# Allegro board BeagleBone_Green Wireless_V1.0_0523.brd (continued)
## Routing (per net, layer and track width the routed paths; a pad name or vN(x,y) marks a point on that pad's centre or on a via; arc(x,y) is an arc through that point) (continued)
BT_AUD_CLK: length 8
  TOP w0.121: U21.1 56.5,107.33 56.89,106.94 59.27,106.94 59.44,106.78 59.44,104.65 TP13.1 60.31,104.3 U18.60
BT_AUD_FSYNC: length 6.2
  TOP w0.121: U21.3 58.2,108.71 59.18,107.72 59.18,107.38 59.68,106.88 59.68,105.9 TP12.1 60.62,105.7 U18.58
BT_AUD_IN: length 5.1
  TOP w0.121: U18.56 60.89,107.1 60.74,107.25 60.49,107.25 60.1,107.65 TP10.1 59.69,108.17 59.69,108.3 58.64,109.35 58.39,109.35 58.04,109.71 U21.5
BT_AUD_OUT: length 5.5
  TOP w0.121: U18.57 TP11.1 59.97,106.8 59.97,106.94 59.44,107.48 59.44,108.18 58.51,109.11 58.29,109.11 58.19,109.21 U21.4
BT_EN: length 11.9
  TOP w0.121: v1(68.17,111.25) 67.86,111.56 67.86,111.58 67.63,111.82 67.56,111.82 67.44,111.94 U18.41
  BOTTOM w0.121: Q3.1 62.98,107.53 64.46,106.05 65.5,106.05 66.73,107.28 66.73,108.23 67.02,108.51 67.02,109.25 67.46,109.69 R188.1 67.46,109.78 67.78,110.1 67.79,110.1 68.17,110.48 v1(68.17,111.25)
BT_HCI_CTS: length 1.3
  TOP w0.121: R184.1 58.65,111.21 U21.8
BT_HCI_RTS: length 1.5
  TOP w0.121: U21.9 58.27,111.71 R183.1
BT_HCI_RX: length 1.4
  TOP w0.121: U21.6 58.04,110.21 58.42,109.83 R186.1
BT_HCI_TX: length 1.3
  TOP w0.121: R185.1 58.69,110.71 U21.7
CAP_VBB_MPU: length 4.2
  TOP w0.121: v1(46.32,88.73) 46.33,88.75 U5.C10
  BOTTOM w0.121: C91.1 46.8,87.54 46.32,88.02 v1(46.32,88.73)
CAP_VDD_SRAM_CORE: length 5.2
  TOP w0.121: U5.D9 v1(47.92,89.54)
  BOTTOM w0.121: C89.1 47.75,87.6 48.32,88.17 48.32,89.13 v1(47.92,89.54)
CAP_VDD_SRAM_MPU: length 5
  TOP w0.121: v1(45.52,89.54) U5.D11
  BOTTOM w0.121: v1(45.52,89.54) 45.92,89.13 45.92,85.39 C90.1
CLKOUT2: length 112.1
  TOP w0.121: v1(49.58,78.31) 49.02,77.75 49.02,75.54 49.03,75.53 49.03,75.44 49.83,74.64 56.78,74.64 59.16,72.26 61.12,72.26 61.77,71.6 66.68,71.6 67.61,70.66 69.88,70.66 70.56,69.98 70.56,68.2 71.73,67.03 P9.41
  LYR4 w0.127: v1(50.14,107.82) 49.76,107.82 49.58,107.65 42.98,107.65 38.35,103.02 38.35,103.02
  LYR4 w0.133: v1(35.56,83.18) 35.61,83.23 35.61,83.37 35.55,83.44 35.55,86.65 34.99,87.2 34.99,88.28 35.75,89.04 35.75,93.48 37.2,94.93 37.2,99.61 36.83,99.98 36.83,101.73 36.65,101.9 36.65,102.48 37.19,103.02 38.35,103.02
  BOTTOM w0.121: v1(49.58,78.31) 49.45,78.44 49.3,78.44 48.97,78.77 43.94,78.77 42.99,79.72 42.99,82.72 43.94,83.67 R20.1 R19.2 42.48,84.81 42.48,85.76 42.29,85.95 41.53,85.95 41.29,85.72 37.68,85.72 37.07,85.1 37.07,84.56 37.48,84.14 37.48,83.45 37.07,83.03 37.07,82.84 37.06,82.83 ; 37.06,82.83 35.91,82.83 v1(35.56,83.18) ; 37.06,82.83 37.31,82.59 P2.18 ; U22.20 65.67,105.35 65.46,105.56 63.5,105.56 63,106.06 61.49,106.06 61.32,106.24 58.63,106.24 56.82,108.05 56.41,108.05 56.4,108.04 55.03,108.04 54.17,107.17
  BOTTOM w0.127: v1(50.14,107.82) 50.14,107.61 50.86,106.9 52.17,106.9 52.44,107.17 54.17,107.17
CLKOUT_SRC: length 5.1
  TOP w0.121: U5.D14 v1(43.12,89.54)
  BOTTOM w0.121: R19.1 42.99,88.11 42.72,88.39 42.72,89.13 v1(43.12,89.54)
DDR_A0: length 23.9
  TOP w0.121: U5.F3 v1(52.72,91.14) ; v1(62.9,85.89) U12.N3
  LYR3 w0.133: v1(55.24,88.24) 54.74,88.24 54.61,88.11 54.61,86.33 56.26,84.68 56.26,84.43 58.42,82.27 62.99,82.27 63.75,83.03 63.75,85.83 63.37,86.21 63.21,86.21 v1(62.9,85.89)
  BOTTOM w0.121: v1(52.72,91.14) 53.12,91.54 53.72,91.54 53.98,91.29 53.98,89.51 v1(55.24,88.24)
DDR_A1: length 24.1
  TOP w0.121: U5.H1 55.94,93.14 57.98,91.1 59.12,91.1 60.32,89.89 v1(60.32,89) ; v1(66.9,85.09) U12.P7
  LYR3 w0.121: 61.59,89 61.9,88.69 63.07,88.69
  LYR3 w0.133: v1(66.9,85.09) 66.54,85.45 66.29,85.45 66.17,85.32 66.17,84.81 66.04,84.68 65.79,84.68 65.66,84.81 65.66,85.32 65.53,85.45 65.41,85.45 65.28,85.32 65.28,84.43 65.41,84.3 65.79,84.3 65.91,84.18 65.91,84.02 65.79,83.9 65.02,83.9 64.9,84.02 64.9,85.57 65.28,85.95 65.28,86.97 64.01,88.24 63.63,88.24 63.18,88.69 63.07,88.69 ; v1(60.32,89) 60.33,89 61.59,89
DDR_A2: length 23.9
  TOP w0.121: v1(62.9,85.09) U12.P3 ; U5.E4 v1(51.92,90.34)
  LYR3 w0.121: v1(62.9,85.09) 62.5,85.49 62.5,87.21
  LYR3 w0.133: 62.5,87.21 62.23,87.48 60.83,87.48 60.45,87.1 58.17,87.1 58.04,87.22 58.04,88.62 58.17,88.75 58.8,88.75 58.9,88.85 58.9,89.28 58.8,89.38 58.17,89.38 58.04,89.51 58.04,90.53 56.11,92.45 55.9,92.45 55.65,92.2 55.65,92.02 56.52,91.16 56.52,90.27 55.75,89.51 52.52,89.51 51.92,90.11 v1(51.92,90.34)
DDR_A3: length 24
  TOP w0.121: v1(52.72,88.73) U5.C3 ; v1(62.1,85.89) U12.N2
  LYR3 w0.121: v1(62.1,85.89) 61.7,86.29 61,86.29
  LYR3 w0.133: 61,86.29 60.96,86.33 57.4,86.33 57.28,86.46 57.28,89.56 57.2,89.64 56.97,89.64 56.9,89.56 56.9,87.32 56.82,87.25 56.46,87.25 56.39,87.17 56.39,86.79 56.31,86.72 56.08,86.72 56.01,86.79 56.01,87.17 55.93,87.25 55.77,87.25 55.69,87.32 55.69,87.53 55.77,87.6 56.44,87.6 56.52,87.68 56.52,87.91 56.44,87.99 55.77,87.99 55.69,88.06 55.69,88.29 55.77,88.37 56.44,88.37 56.52,88.44 56.52,88.66 56.44,88.73 54.36,88.73 54.23,88.61 54.23,87.48 54.1,87.35 53.85,87.35 53.72,87.48 53.72,88.61 53.59,88.73 v1(52.72,88.73)
DDR_A4: length 23.9
  TOP w0.121: v1(67.7,85.09) U12.P8 ; v1(57.53,81.38) 57.91,81.76 57.91,82.14 55.12,84.94 55.12,85.7 54.36,86.46 54.36,87.66 54.08,87.94 53.75,87.94 53.51,88.18 53.51,88.74 U5.C2
  LYR3 w0.121: 66.68,84.69 67.3,84.69 v1(67.7,85.09)
  LYR3 w0.133: 66.68,84.69 66.42,84.43 66.42,82.14 66.17,81.89 64.52,81.89 63.75,81.13 57.78,81.13 v1(57.53,81.38)
DDR_A5: length 23.9
  TOP w0.121: U5.B1 54.13,88.34 54.74,87.73 54.74,87.35 54.86,87.22 v1(55.24,87.22) ; v1(62.1,85.09) U12.P2
  LYR3 w0.121: v1(62.1,85.09) 62.5,84.69 62.5,83.3 62.48,83.29
  LYR3 w0.133: v1(55.24,87.22) 55.69,86.78 55.69,86.33 55.94,86.08 56.57,86.08 56.64,86.16 56.64,86.77 56.72,86.84 56.95,86.84 57.02,86.77 57.02,84.81 57.15,84.68 57.4,84.68 57.53,84.81 57.53,85.83 57.66,85.95 57.91,85.95 58.04,85.83 58.04,83.67 58.29,83.41 58.93,83.41 59.05,83.54 59.05,85.83 59.18,85.95 60.58,85.95 60.71,85.83 60.71,83.16 60.83,83.03 62.23,83.03 62.48,83.29
DDR_A6: length 24.1
  TOP w0.121: v1(67.7,84.29) U12.R8 ; v1(51.12,89.54) U5.D5
  BOTTOM w0.121: v1(67.7,84.29) 67.3,83.89 67.3,83.27 65.91,81.89 58.67,81.89 56.77,83.79 56.77,86.33 55.37,87.73 54.99,87.73 52.79,89.93 51.52,89.93 v1(51.12,89.54)
DDR_A7: length 24.1
  TOP w0.121: v1(62.1,84.29) U12.R2 ; v1(58.55,85.04) 59.03,84.56 59.56,84.56 59.69,84.43 59.69,83.16 59.56,83.03 58.8,83.03 57.02,84.81 57.02,89 55.75,90.27 55.75,90.91 55.52,91.14 53.52,91.14 U5.E2
  BOTTOM w0.121: v1(62.1,84.29) U12.R2 63.63,84.69 63.75,84.82 63.75,85.36 63.63,85.49 61,85.49 60.55,85.04 v1(58.55,85.04)
DDR_A8: length 23.9
  TOP w0.121: v1(67.7,83.49) U12.T8 ; v1(51.92,89.54) U5.D4
  BOTTOM w0.121: v1(51.92,89.54) 52.68,89.54 53.34,88.87 53.34,86.44 53.59,86.19 56.01,86.19 56.39,85.81 56.39,83.67 58.55,81.51 66.04,81.51 67.7,83.17 v1(67.7,83.49)
DDR_A9: length 24
  TOP w0.121: U5.C1 54.48,88.57 54.48,88.44 55.19,87.73 55.5,87.73 55.64,87.59 55.64,86.07 55.53,85.95 55.36,85.95 55.24,86.07 v1(55.24,86.59) ; v1(62.9,84.29) U12.R3
  LYR3 w0.133: v1(55.24,86.59) 55.24,86.21 55.75,85.7 56.39,85.7 56.64,85.45 56.64,84.56 58.55,82.65 59.44,82.65 59.56,82.78 59.56,85.45 59.69,85.57 60.07,85.57 60.2,85.45 60.2,82.78 60.32,82.65 62.87,82.65 63.37,83.16 63.37,84.56 63.25,84.68 63.02,84.68 62.9,84.56 v1(62.9,84.29)
DDR_A10: length 24
  TOP w0.121: v1(66.9,87.49) U12.L7 ; U5.F4 v1(51.92,91.14)
  LYR3 w0.121: 53.08,91.54 52.32,91.54 v1(51.92,91.14)
  LYR3 w0.133: v1(66.9,87.49) 67.18,87.78 67.18,87.99 67.06,88.11 66.17,88.11 66.04,88.24 66.04,88.49 66.17,88.62 67.06,88.62 67.18,88.75 67.18,89 67.06,89.13 65.79,89.13 63.75,91.16 60.71,91.16 59.12,92.75 58.23,92.75 57.14,93.83 53.98,93.83 53.59,93.45 53.59,92.05 53.08,91.54
DDR_A11: length 23.9
  TOP w0.121: U5.F2 53.52,91.94 v1(55.24,91.94) ; v1(66.9,84.29) U12.R7
  BOTTOM w0.121: v1(55.24,91.94) 54.74,91.43 54.74,89.89 56.01,88.62 57.28,88.62 57.53,88.37 57.53,84.05 58.93,82.65 65.53,82.65 66.17,83.29 66.17,84.04 66.42,84.29 v1(66.9,84.29)
DDR_A12: length 24.1
  TOP w0.121: v1(66.9,85.89) U12.N7 ; v1(52.72,90.34) U5.E3
  LYR3 w0.133: v1(52.72,90.34) 52.78,90.27 55.5,90.27 55.75,90.53 55.75,90.91 55.5,91.16 54.61,91.16 54.36,91.41 54.36,92.81 54.61,93.07 56.52,93.07 58.04,91.54 59.31,91.54 60.95,89.9 62.62,89.9 62.87,90.14 63.63,90.14 65.28,88.49 65.28,87.51 v1(66.9,85.89)
DDR_A13: length 24
  TOP w0.121: v1(62.9,83.49) U12.T3 ; U5.H3 v1(52.72,92.74)
  BOTTOM w0.121: v1(52.72,92.74) 55.32,92.74 55.75,92.3 55.75,89.38 56.13,89 57.66,89 57.91,88.75 57.91,84.18 59.05,83.03 64.77,83.03 64.9,83.16 64.9,83.36 64.77,83.49 v1(62.9,83.49)
DDR_A14: length 24
  TOP w0.121: v1(66.9,83.49) U12.T7 ; v1(51.92,92.74) U5.H4
  BOTTOM w0.121: v1(66.9,83.49) 65.68,82.27 58.8,82.27 57.15,83.92 57.15,86.97 54.36,89.76 54.36,91.92 53.94,92.34 52.29,92.34 51.92,92.71 v1(51.92,92.74)
DDR_A15: length 24
  TOP w0.121: U12.M7 65.91,86.51 65.91,83.24 65.37,82.69 64.27,82.69 63.37,81.79 58.75,81.79 56.01,84.53 56.01,88.49 54.97,89.53 52.72,89.53 U5.D3
DDR_BA0: length 24.1
  TOP w0.121: U5.C4 v1(51.92,88.73) ; v1(62.1,86.69) U12.M2
  LYR3 w0.121: 51.52,87.6 51.52,88.61 51.64,88.73 v1(51.92,88.73) ; 52.32,88.87 52.32,87.6
  LYR3 w0.133: 51.52,87.6 51.52,86.59 51.64,86.46 51.82,86.46 51.94,86.59 51.94,86.97 52.07,87.1 52.32,87.1 52.45,86.97 52.45,86.59 52.58,86.46 52.83,86.46 52.96,86.59 52.96,87.35 52.83,87.48 52.44,87.48 52.32,87.6 ; 52.32,88.87 52.32,89.01 52.44,89.14 55.89,89.14 56.9,90.14 56.9,90.78 56.99,90.88 57.18,90.88 57.66,90.4 57.66,87.1 58.04,86.72 60.58,86.72 60.96,87.1 61.97,87.1 62.1,86.97 v1(62.1,86.69)
DDR_BA1: length 24.1
  TOP w0.121: v1(67.7,85.89) U12.N8 ; U5.E1 v1(55.24,90.74)
  LYR3 w0.133: v1(55.24,90.74) 54.02,90.74 53.72,91.03 53.72,91.41 53.98,91.67 53.98,93.19 54.23,93.45 56.77,93.45 58.33,91.88 59.47,91.88 61.09,90.27 62.48,90.27 62.61,90.4 62.61,90.65 62.74,90.78 63.5,90.78 65.63,88.65 65.63,87.76 66.45,86.94 67.06,86.94 67.22,86.78 67.22,86.37 v1(67.7,85.89)
DDR_BA2: length 24.1
  TOP w0.121: v1(62.9,86.69) U12.M3 ; v1(52.72,87.93) U5.B3
  LYR3 w0.133: v1(62.9,86.69) 63.37,86.69 63.5,86.82 63.5,87.22 63.63,87.35 63.88,87.35 64.14,87.1 64.14,86.72 63.88,86.46 63.88,86.21 64.14,85.95 64.14,82.65 63.37,81.89 58.29,81.89 55.88,84.3 55.88,84.56 54.1,86.33 53.91,86.33 53.78,86.21 53.78,85.95 53.66,85.83 53.47,85.83 53.34,85.95 53.34,88.11 53.21,88.24 53.02,88.24 v1(52.72,87.93)
DDR_CASN: length 24
  TOP w0.121: v1(58.55,87.6) 58.55,86.84 58.67,86.72 59.56,86.72 59.69,86.59 59.69,86.08 59.56,85.95 59.44,85.95 59.31,85.83 59.31,85.57 59.44,85.45 59.56,85.45 59.69,85.32 59.69,85.06 59.56,84.94 59.07,84.94 58.95,85.06 58.95,86.33 58.82,86.46 58.17,86.46 58.04,86.33 58.04,84.94 57.91,84.81 57.53,84.81 57.4,84.94 57.4,89.76 57.28,89.89 56.77,89.89 56.13,90.53 56.13,91.28 55.88,91.54 U5.F1 ; v1(62.9,88.29) U12.K3
  LYR3 w0.133: v1(58.55,87.6) 60.45,87.6 60.71,87.86 62.46,87.86 v1(62.9,88.29)
DDR_CKE: length 25.1
  TOP w0.121: U5.G3 v1(52.72,91.94) ; v1(68.5,88.29) U12.K9
  LYR3 w0.133: v1(52.72,91.94) 53.21,92.43 53.21,93.95 53.09,94.08 52.58,94.08 52.45,94.21 52.45,94.46 52.58,94.59 54.23,94.59 54.61,94.21 57.28,94.21 58.42,93.07 59.31,93.07 60.83,91.54 64.01,91.54 66.04,89.51 68.58,89.51 68.71,89.38 68.71,88.5 v1(68.5,88.29)
  BOTTOM w0.121: R96.2 v1(68.5,88.29)
DDR_CLK: length 24
  TOP w0.095: U12.J7 66.33,89.33 66.14,89.33 65.15,88.34 65.15,84.82 62.98,82.65 58.82,82.65 56.67,84.8 56.67,88.85 55.19,90.32 53.76,90.32 53.37,89.94 U5.D2
DDR_CLKN: length 24
  TOP w0.095: U5.D1 54.02,90.04 55.08,90.04 56.39,88.73 56.39,84.68 58.7,82.37 63.09,82.37 65.43,84.71 65.43,88.23 66.25,89.05 66.77,89.05 66.87,88.94 66.87,88.79 66.77,88.69 U12.K7
DDR_CSN: length 23.9
  TOP w0.121: U5.H2 53.52,93.54 56.04,93.54 58.1,91.48 59.25,91.48 60.83,89.89 60.83,88.57 60.76,88.49 60.27,88.49 60.2,88.42 60.2,87.22 60.45,86.97 60.45,83.54 60.57,83.41 60.71,83.41 60.83,83.54 60.83,87.1 60.58,87.35 60.58,87.91 60.66,87.99 60.88,87.99 60.96,87.91 60.96,87.56 61.04,87.49 62.09,87.49 U12.L2
DDR_D0: length 23.3
  TOP w0.121: v1(52.72,96.74) U5.M3 ; v1(63.7,93.09) U12.E3
  LYR3 w0.133: v1(63.7,93.09) 63.7,94.84 63.82,94.97 64.26,94.97 64.39,94.84 64.39,92.56 64.52,92.43 65.02,92.43 65.15,92.56 65.15,94.72 61.85,98.02 54.36,98.02 53.07,96.74 v1(52.72,96.74)
DDR_D1: length 23.3
  TOP w0.121: v1(51.92,96.74) U5.M4 ; v1(66.9,92.29) U12.F7
  LYR3 w0.121: 67.87,90.28 68.1,90.52 68.1,90.86 68.1,91.66 67.86,91.89 67.3,91.89 v1(66.9,92.29) ; v1(51.92,96.74) 52.32,96.34 52.32,95.77 52.55,95.54 54.17,95.54
  LYR3 w0.133: 54.17,95.54 55.12,94.59 57.66,94.59 58.17,94.08 58.8,94.08 61,91.88 64.3,91.88 66.29,89.9 67.48,89.9 67.87,90.28
DDR_D2: length 23.3
  TOP w0.121: U5.N1 56.89,97.14 57.28,96.75 58.42,96.75 58.55,96.88 58.55,97.76 58.42,97.89 56.26,97.89 56.13,98.02 56.13,98.27 56.26,98.4 62.48,98.4 62.61,98.27 62.61,97.26 64.13,95.74 64.13,92.56 63.86,92.29 63.38,92.29 63.37,92.29 62.9,92.29 U12.F2
DDR_D3: length 23.3
  TOP w0.121: U5.N2 53.52,97.54 57.25,97.54 v1(57.53,97.26) ; v1(67.7,92.29) U12.F8
  BOTTOM w0.121: v1(67.7,92.29) 68.1,92.69 68.1,93.29 67.9,93.49 67.31,93.49 66.97,93.83 66.17,93.83 66.04,93.7 66.04,92.81 65.91,92.68 65.66,92.68 65.53,92.81 65.53,93.7 65.41,93.83 65.15,93.83 65.02,93.7 65.02,92.81 64.9,92.68 64.71,92.68 64.58,92.81 64.58,93.38 63.75,94.21 63.75,95.73 62.23,97.26 v1(57.53,97.26)
DDR_D4: length 23.3
  TOP w0.121: U5.N3 v1(52.72,97.54) ; U12.H3 64.92,90.29 65.66,91.03 65.66,96.88 64.77,97.76 v1(63.75,97.76)
  LYR3 w0.133: v1(63.75,97.76) 62.74,98.78 53.98,98.78 52.73,97.54 v1(52.72,97.54)
DDR_D5: length 23.3
  TOP w0.121: v1(67.7,90.69) U12.H8 ; U5.N4 v1(51.92,97.54)
  LYR3 w0.121: v1(51.92,97.54) 52.32,97.14 52.97,97.14
  LYR3 w0.133: 52.97,97.14 54.23,98.4 62.1,98.4 65.66,94.84 65.66,91.16 66.55,90.27 67.28,90.27 v1(67.7,90.69)
DDR_D6: length 23.3
  TOP w0.121: U5.P3 v1(52.72,98.34) ; U12.G2 62.9,90.69 64.81,90.69 65.28,91.16 65.28,96.37 v1(64.39,97.26)
  LYR3 w0.133: v1(52.72,98.34) 53.02,98.34 53.85,99.16 62.99,99.16 64.39,97.76 v1(64.39,97.26)
DDR_D7: length 23.3
  TOP w0.121: U5.P4 v1(51.92,98.34) ; v1(66.9,90.69) U12.H7
  LYR3 w0.121: 53.02,98.74 52.32,98.74 v1(51.92,98.34)
  LYR3 w0.133: 53.02,98.74 53.8,99.52 63.27,99.52 66.17,96.62 66.17,91.42 v1(66.9,90.69)
DDR_D8: length 20.3
  TOP w0.121: U5.J1 56.15,93.94 58.23,91.86 60.26,91.86 60.77,91.35 60.77,90.46 61.34,89.89 63.63,89.89 63.75,89.76 63.75,88.37 63.88,88.24 64.39,88.24 66.04,89.89 66.04,93.03 U12.D7
DDR_D9: length 20.3
  TOP w0.121: v1(57.53,95.1) 57.17,94.74 U5.K1 ; v1(62.9,94.69) U12.C3
  LYR3 w0.133: v1(62.9,94.69) 62.9,93.95 62.77,93.83 60.71,93.83 60.58,93.95 60.58,97.13 60.45,97.26 59.94,97.26 59.82,97.13 59.82,94.97 59.69,94.84 59.18,94.84 59.05,94.97 59.05,97.13 58.93,97.26 58.17,97.26 58.04,97.13 58.04,95.22 57.91,95.1 v1(57.53,95.1)
DDR_D10: length 20.3
  TOP w0.121: v1(67.7,94.69) U12.C8 ; U5.K2 53.52,95.14 v1(55.24,95.14)
  BOTTOM w0.121: v1(55.24,95.14) 55.72,95.14 55.88,94.97 56.52,94.97 56.64,95.1 56.64,97.26 57.15,97.76 62.23,97.76 64.14,95.86 64.14,94.46 64.39,94.21 67.21,94.21 v1(67.7,94.69)
DDR_D11: length 20.1
  TOP w0.121: v1(62.1,94.69) U12.C2 ; v1(52.72,95.14) U5.K3
  BOTTOM w0.121: v1(52.72,95.14) 52.5,94.92 52.5,94.71 52.62,94.59 54.23,94.59 54.36,94.72 54.36,95.35 54.46,95.46 54.69,95.46 54.81,95.34 54.81,94.77 54.99,94.59 56.64,94.59 57.15,94.08 58.83,94.08 58.95,93.96 58.95,93.14 59.21,92.89 61.47,92.89 61.64,93.06 61.64,93.45 61.52,93.57 59.56,93.57 59.44,93.7 59.44,93.95 59.56,94.08 62.27,94.08 62.39,94.2 62.39,94.39 v1(62.1,94.69)
DDR_D12: length 20.2
  TOP w0.121: v1(66.9,96.29) U12.A7 ; U5.K4 v1(51.92,95.14)
  BOTTOM w0.121: v1(66.9,96.29) 66.9,96.65 64.71,98.84 55.94,98.84 53.98,96.88 53.98,95.29 53.85,95.16 53.59,95.16 53.47,95.29 53.47,95.41 53.34,95.54 52.32,95.54 v1(51.92,95.14)
DDR_D13: length 20.2
  TOP w0.121: v1(62.1,96.29) U12.A2 ; v1(52.72,95.94) U5.L3
  LYR3 w0.133: v1(62.1,96.29) 62.1,96.3 62.1,97.13 61.57,97.66 54.61,97.66 54.48,97.54 54.48,97.13 54.61,97 56.9,97 57.02,96.88 57.02,95.22 56.9,95.1 55.88,95.1 55.75,95.22 55.75,96.24 55.63,96.37 53.47,96.37 53.04,95.94 v1(52.72,95.94)
DDR_D14: length 20.3
  TOP w0.121: U5.L4 v1(51.92,95.94) ; v1(67.7,95.49) U12.B8
  BOTTOM w0.121: v1(67.7,95.49) 67.3,95.89 67.3,96.76 64.9,99.16 55.75,99.16 52.93,96.34 52.32,96.34 v1(51.92,95.94)
DDR_D15: length 20.1
  TOP w0.121: U12.A3 61.42,97.76 59.44,97.76 59.31,97.64 59.31,97.38 59.44,97.26 60.71,97.26 60.83,97.13 60.83,96.88 60.71,96.75 59.44,96.75 59.31,96.62 59.31,96.37 59.44,96.24 60.71,96.24 60.83,96.11 60.83,95.86 60.71,95.73 57.15,95.73 57.02,95.61 57.02,95.35 56.9,95.22 55.88,95.22 55.75,95.35 55.75,95.73 55.88,95.86 56.26,95.86 56.39,95.99 56.39,96.21 56.26,96.34 54.74,96.34 U5.M1
DDR_DQM0: length 23.3
  TOP w0.121: U5.M2 53.52,96.74 56.65,96.74 57.1,96.29 v1(57.53,96.29) ; v1(66.9,93.09) U12.E7
  BOTTOM w0.121: v1(66.9,93.09) 66.55,93.09 66.42,92.96 66.42,92.43 66.29,92.3 64.26,92.3 64.14,92.43 64.14,93.32 63.37,94.08 63.37,95.61 62.1,96.88 58.17,96.88 58.04,96.75 58.04,94.72 57.91,94.59 57.15,94.59 57.02,94.72 57.02,96.16 57.15,96.29 v1(57.53,96.29)
DDR_DQM1: length 20.2
  TOP w0.121: U12.D3 62.9,93.89 61.4,93.89 60.83,93.32 59.18,93.32 59.05,93.45 59.05,93.7 59.18,93.83 60.71,93.83 60.83,93.95 60.83,94.21 60.71,94.34 59.18,94.34 59.05,94.46 59.05,94.72 59.18,94.84 60.71,94.84 60.83,94.97 60.83,95.22 60.71,95.35 58.17,95.35 58.04,95.22 58.04,94.46 57.91,94.34 53.52,94.34 U5.J2
DDR_DQS0: length 23.3
  TOP w0.095: U12.F3 63.02,91.89 62.94,91.81 62.94,91.57 63.02,91.49 63.61,91.49 63.69,91.57 63.69,91.85 63.77,91.93 64,91.93 64.07,91.85 64.07,91.45 64.15,91.37 64.33,91.37 64.62,91.66 64.62,95.87 63.09,97.4 63.09,98.11 63.4,98.43 64.39,98.43 64.52,98.56 64.52,98.78 64.39,98.91 56.02,98.91 55.15,98.04 54.02,98.04 U5.P1
DDR_DQS1: length 20.3
  TOP w0.095: U5.L1 54.84,95.54 v1(55.24,95.94)
  TOP w0.121: v1(66.9,94.69) U12.C7
  BOTTOM w0.095: v1(66.9,94.69) 66.94,94.69 67.01,94.77 67.01,95.02 66.94,95.1 65.04,95.1 64.74,95.39 64.74,95.98 65.04,96.27 65.3,96.27 65.53,96.49 65.53,96.88 64.26,98.15 56.15,98.15 55.78,97.78 55.78,97.55 56.16,97.17 56.16,96.79 55.87,96.49 55.14,96.49 55.02,96.37 55.02,96.16 v1(55.24,95.94)
DDR_DQSN0: length 23.3
  TOP w0.095: U5.P2 53.5,98.32 55.04,98.32 55.91,99.19 64.5,99.19 64.8,98.9 64.8,98.44 64.5,98.15 63.52,98.15 63.37,98 63.37,97.52 64.9,95.99 64.9,91.54 64.45,91.09 U12.G3
DDR_DQSN1: length 20.3
  TOP w0.095: v1(54.48,95.94) 53.52,95.94 U5.L2
  TOP w0.121: v1(66.9,95.49) U12.B7
  BOTTOM w0.095: v1(66.9,95.49) 66.78,95.38 65.15,95.38 65.02,95.5 65.02,95.86 65.15,95.99 65.42,95.99 65.81,96.38 65.81,96.99 64.37,98.43 56.04,98.43 55.5,97.89 55.5,97.43 55.88,97.05 55.88,96.9 55.75,96.77 55.03,96.77 54.74,96.48 54.74,96.19 v1(54.48,95.94)
DDR_ODT: length 24.1
  TOP w0.121: v1(59.31,89) 59.44,88.87 59.44,87.22 59.31,87.1 59.07,87.1 58.95,87.22 58.95,88.6 58.8,88.75 58.8,89.38 58.69,89.49 58.26,89.49 58.15,89.38 58.15,86.82 58.04,86.72 57.89,86.72 57.78,86.82 57.78,90.02 57.53,90.27 56.9,90.27 56.52,90.65 56.52,91.54 55.72,92.34 55.08,92.34 U5.G1 ; v1(61.3,88.29) U12.K1
  LYR3 w0.133: v1(59.31,89) 59.31,89.51 59.05,89.76 59.05,90.14 59.18,90.27 59.56,90.27 59.82,90.02 59.82,88.62 59.69,88.49 59.44,88.49 59.31,88.37 59.31,88.11 59.44,87.99 60.32,87.99 60.63,88.29 v1(61.3,88.29)
DDR_RASN: length 24
  TOP w0.121: v1(62.9,89.09) U12.J3 ; U5.G4 v1(51.92,91.94)
  LYR3 w0.121: 52.73,89.89 52.57,89.89 52.32,90.14 52.32,90.53 52.11,90.74 51.73,90.74 51.52,90.95 51.52,91.54 v1(51.92,91.94)
  LYR3 w0.133: 52.73,89.89 55.63,89.89 56.13,90.4 56.13,91.03 55.64,91.53 54.86,91.53 54.74,91.66 54.74,92.56 54.86,92.68 56.39,92.68 57.89,91.18 59.16,91.18 60.82,89.52 62.75,89.52 62.99,89.76 63.5,89.76 64.24,89.03 64.24,88.85 64.09,88.7 63.91,88.7 63.52,89.09 v1(62.9,89.09)
DDR_RESETN: length 20.7
  TOP w0.121: U12.T2 v1(62.1,83.49) 61.64,83.03 60.2,83.03 60.07,83.16 60.07,86.84 59.82,87.1 59.82,89.76 59.29,90.29 58.15,90.29 57.78,90.65 57.15,90.65 56.9,90.91 56.9,91.67 55.83,92.74 53.52,92.74 U5.G2
  BOTTOM w0.121: R97.2 63.75,84.29 63.35,83.89 U12.T2 v1(62.1,83.49)
DDR_VREF: length 27.1
  TOP w0.305: v1(67.7,86.69) U12.M8 ; v1(61.3,90.69) U12.H1 ; v1(51.92,93.54) U5.J4
  BOTTOM w0.381: R98.2 63.79,90.69 63.22,90.12 61.87,90.12 v1(61.3,90.69) ; R98.2 64.39,91.24 63.91,91.72 61.74,91.72 61.73,91.73 60.87,91.73 60.76,91.62 57.71,91.62 56.77,92.56 C28.1 56.43,93.54 55.88,94.08 52.46,94.08 v1(51.92,93.54) ; R98.2 C123.1 64.39,89.13 64.62,88.89 64.85,88.89 64.86,88.89 65.02,88.89 65.41,88.51 R100.1 C124.1 66.17,87.09 66.57,86.69 v1(67.7,86.69)
DDR_VTP: length 6.7
  TOP w0.305: v1(52.72,93.54) U5.J3
  BOTTOM w0.381: v1(52.72,93.54) 55.54,93.54 56.26,92.81 56.26,91.29 R22.2
DDR_WEN: length 23.9
  TOP w0.121: v1(56.77,82.65) 56.77,82.8 54.86,84.71 54.86,85.45 54.36,85.95 53.64,85.95 53.51,86.08 53.51,87.7 53.12,88.1 U5.B2 ; v1(62.9,87.49) U12.L3
  LYR3 w0.133: v1(56.77,82.65) 56.78,82.65 57.03,82.65 58.17,81.51 63.63,81.51 64.52,82.4 64.52,85.7 64.9,86.08 64.9,86.84 63.88,87.86 63.27,87.86 v1(62.9,87.49)
EHRPWM1A: length 44.2
  TOP w0.121: v1(41.88,104.52) 42.36,104.52 43.92,102.96 43.92,100.74 U5.U14
  LYR4 w0.133: v1(41.88,104.52) 41.68,104.31 41.68,102.8 41.38,102.5 41.38,101.42 41.29,101.34 41.29,101.21 39.7,99.62 39.7,99.12 39.24,98.65 39.24,98.05 39.49,97.8 39.49,93.69 39.19,93.39 39.19,92.33 38.18,91.31 38.17,91.31 37.22,90.37 37.22,87.89 37.26,87.86 37.26,87.58 37.07,87.39 37.07,84.99 37.06,84.98 37.06,84.64 37.3,84.4 37.77,84.4 38.26,83.92 38.26,71.51 P9.14
EHRPWM1B: length 38.8
  TOP w0.121: v1(43.12,99.94) U5.T14
  LYR4 w0.133: v1(43.12,99.94) 43.12,100.49 42.48,101.12 42.04,101.12 40.31,99.39 40.31,92.25 38.61,90.55 38.07,90.55 37.69,90.17 37.69,88.24 38.23,87.71 38.23,86.31 38.83,85.71 38.83,79.28 41.58,76.53 41.58,76.33 39.6,74.35 39.6,70.38 38.86,69.65 P9.16
EHRPWM2A: length 17.3
  TOP w0.121: U5.U10 47.12,100.74 47.12,101.3 47.35,101.53 47.36,101.53 47.49,101.66 47.49,102.11 47.14,102.46 47.14,103.48 47.05,103.57 47.05,103.62 45.75,104.92 45.75,105.71 44.6,106.86 44.6,111.91 43.27,113.24 43.27,114.62 P8.19
EHRPWM2B: length 26.3
  TOP w0.121: v1(46.32,99.94) U5.T10
  LYR3 w0.133: P8.13 35.65,114.61 35.21,114.61 33.91,113.31 33.91,112.22 34.82,111.3 37.04,111.3 37.05,111.3 41.64,111.3 43.03,109.91 43.03,108.74 44.1,107.67 44.1,106.35 44.75,105.69 44.75,102.08 44.77,102.06 44.77,101.84 45.78,100.83 45.78,100.48 v1(46.32,99.94)
EMMC_RSTN: length 5.2
  TOP w0.076: v1(30.56,108.81) 30.03,108.29 U13.K5
  BOTTOM w0.121: R162.2 R111.2 28.96,107.54 28.96,107.42 29.19,107.19 29.61,107.19 29.65,107.22 29.66,107.22 29.89,107.45 29.89,107.46 30.05,107.62 30.05,108.31 v1(30.56,108.81)
EMMC_VCCI: length 4.4
  TOP w0.076: 32.9,110.85 33.27,110.47 33.24,110.45 33.24,110.03 U13.C2
  TOP w0.121: v1(30.61,110.9) 32.85,110.9 32.9,110.85
  BOTTOM w0.121: C125.1 v1(30.61,110.9)
ENZ_KALDO_1P8V: length 3.4
  TOP w0.121: U5.B4 v1(51.92,87.93)
  BOTTOM w0.121: R54.2 52.51,87.34 v1(51.92,87.93)
GPIO0_7: length 48
  TOP w0.121: v1(49.61,77.7) 49.28,77.37 49.28,75.54 49.93,74.89 56.88,74.89 56.99,74.78 57.02,74.78 59.26,72.54 61.24,72.54 61.93,71.86 67.03,71.86 67.89,70.99 70.21,70.99 71.63,69.57 P9.42 ; v1(37.59,82.99) 37.97,82.99 38.05,82.91 R50.1
  BOTTOM w0.121: v1(37.59,82.99) 37.59,83.12 37.73,83.26 37.73,84.44 37.86,84.58 37.86,85.08 38.1,85.32 38.61,85.32 39.24,84.68 40.77,84.68 41.15,84.3 R51.1 42.04,83.67 42.67,83.03 42.67,79.63 43.87,78.44 48.77,78.44 49.5,77.7 v1(49.61,77.7)
GPIO0_7SRC: length 7.9
  TOP w0.121: U5.C18 40.01,89.14 38.48,87.6 38.48,86.59 37.01,85.12 37.01,84.63 37.34,84.3 38.23,84.3 R50.2
GPIO0_26: length 57.3
  TOP w0.121: v1(45.52,99.94) U5.T11
  LYR3 w0.133: P8.14 35.05,116.56 35.05,114.91 33.67,113.53 33.67,112.12 34.9,110.9 40.34,110.9 43.81,107.43 43.81,106.23 44.5,105.54 44.5,102.07 44.51,102.06 44.51,101.62 45.52,100.61 v1(45.52,99.94)
  LYR4 w0.121: v1(64.47,111.35) 64.06,111.76 58.67,111.76 57.25,110.34 57.25,106.96 56.57,106.27 v1(55.42,106.27)
  LYR4 w0.133: v1(55.42,106.27) 55.15,106 55.15,105.6 53.65,104.09 46.66,104.09 45.52,102.94 v1(45.52,99.94)
  BOTTOM w0.121: R189.1 R187.2 v1(64.47,111.35)
GPIO0_27: length 54.9
  TOP w0.121: U5.U12 45.51,100.73 45.51,101.84 45.06,102.29 45.06,103.22 44.68,103.6 44.68,105.53 44.63,105.58 44.63,105.59 44.23,105.98 44.23,108.67 44.19,108.72 44.19,109.31 44.09,109.4 44.09,110.29 v1(44.12,110.31) 44.12,111.62 41.4,114.34 P8.17
  LYR3 w0.133: P8.17 41.63,115.29 42.6,114.33 53.31,114.33 v1(53.98,113.67)
  BOTTOM w0.121: U22.18 64.16,103.97 63.56,104.56 61.84,104.56 61.7,104.7 61.7,105.51 61.21,105.99 58.53,105.99 56.72,107.8 56.51,107.8 56.5,107.79 55.14,107.79 54.27,106.92 52.77,106.92 52.42,106.57 50.83,106.57 50.76,106.65 50.75,106.65 49.98,107.42 49.97,107.42 49.74,107.66 49.74,107.66 46.92,110.49 44.67,110.49 44.5,110.31 v1(44.12,110.31)
GPIO1_12: length 51.6
  TOP w0.121: v1(44.72,99.94) U5.T12
  LYR3 w0.133: P8.12 32.83,116.87 32.83,112.11 34.57,110.36 40.18,110.36 43.12,107.42 43.12,106.31 43.28,106.15 43.28,105.97 43.89,105.36 43.89,102.09 43.92,102.06 43.92,101.27 44.72,100.47 v1(44.72,99.94)
  LYR4 w0.133: v1(44.72,99.94) 44.72,100.06 45.21,100.56 45.21,102.97 46.61,104.37 53.59,104.37 54.92,105.69 54.92,106.61 55.17,106.86 v1(55.55,106.86)
  BOTTOM w0.121: 56.37,106.21 58.85,103.73 60.43,103.73 62.08,102.08 R206.1
  BOTTOM w0.133: v1(55.55,106.86) 55.98,106.43 56.16,106.43 56.37,106.21
GPIO1_13: length 50.8
  TOP w0.121: v1(44.72,99.14) U5.R12
  LYR3 w0.121: v1(44.72,99.14) 45.12,99.54 45.12,100.53
  LYR3 w0.133: P8.11 33.44,114.95 33.44,112.02 34.84,110.62 40.26,110.62 40.28,110.6 40.28,110.6 43.36,107.52 43.36,107.52 43.56,107.31 43.56,106.07 44.2,105.44 44.2,101.45 45.12,100.53
  LYR4 w0.121: v1(44.72,99.14) 44.32,99.54 44.32,100.7 44.32,100.71
  LYR4 w0.133: v1(56.29,106.83) 55.85,107.26 55.38,107.26 55.21,107.09 55.07,107.09 54.68,106.71 54.68,105.89 53.44,104.65 46.51,104.65 44.32,102.46 44.32,100.71
  BOTTOM w0.121: R205.1 62.1,102.97 61.09,103.99 59.13,103.99 v1(56.29,106.83)
GPIO1_14: length 40.8
  TOP w0.121: P8.16 37.91,116.88 37.91,114.74 41.5,111.15 41.5,109.95 42.01,109.44 v1(42.62,109.44) 42.62,108.97 43.46,108.13 43.46,105.71 43.49,105.68 43.49,105.67 43.94,105.22 43.94,103.29 44.32,102.91 U5.V13
  BOTTOM w0.121: 54.95,106.87 55.37,107.29 56.46,107.29 59.26,104.5 R204.1 ; 53.1,106.42 52.76,106.08 50.62,106.08 46.71,109.98 45.26,109.98 44.97,109.69 44.36,109.69 44.27,109.59 43.15,109.59 43,109.44 v1(42.62,109.44)
  BOTTOM w0.127: 54.95,106.87 54.5,106.42 53.1,106.42
GPIO1_15: length 39.1
  TOP w0.121: P8.15 38.86,114.5 41.94,111.43 v1(41.94,110.08) 42.54,110.08 43.1,109.52 43.1,109.07 43.74,108.43 43.74,105.77 44.19,105.32 44.19,103.39 44.56,103.02 44.56,101.84 44.71,101.69 44.71,100.73 U5.U13
  BOTTOM w0.121: v1(41.94,110.08) 42.31,110.08 42.56,109.84 44.16,109.84 44.26,109.93 44.87,109.93 45.16,110.23 46.81,110.23 46.83,110.21 46.84,110.21 49.87,107.18 49.87,107.18 50.72,106.32 52.6,106.32 52.95,106.67 54.4,106.67 54.85,107.12 54.85,107.12 55.27,107.54 55.8,107.54 55.8,107.54 56.62,107.54
  BOTTOM w0.133: 56.62,107.54 58.78,105.38 R203.1
GPIO1_16: length 45.1
  LYR4 w0.133: P9.15 37.72,68.17 36.37,68.17 35.33,69.21 35.33,70.67 36.09,71.43 36.09,71.63 37.06,72.59 37.06,72.6 37.3,72.83 37.3,72.83 38,73.53 38,83.84 37.67,84.17 37.2,84.17 36.82,84.54 36.82,85.08 36.84,85.09 36.84,87.49 36.98,87.64 36.98,90.7 37.74,91.47 37.74,92.05 38.96,93.26 38.96,93.49 39.26,93.79 39.26,97.7 39,97.95 39,98.81 39.41,99.23 39.41,99.7 39.42,99.71 39.42,99.72 40.51,100.81 40.51,102.87 41.22,103.58 41.22,104.57 v1(41.83,105.18)
  BOTTOM w0.121: R160.2 v1(41.83,105.18)
GPIO1_17: length 49.7
  TOP w0.121: P9.23 47.65,68.4 47.65,69.74 46.57,70.83 45.71,70.83 45.16,71.37 43.17,71.37 42.55,72 42.55,75.49 41.61,76.43 v1(41.1,76.43) ; U5.V14 43.52,102.8 v1(42.23,104.08)
  LYR4 w0.127: 40.03,99.52 40.03,99.08 39.75,98.8
  LYR4 w0.133: 39.75,98.8 39.47,98.52 39.47,98.18 39.75,97.9 39.75,92.28 38.38,90.91 38.1,90.91 37.46,90.27 37.46,87.99 37.95,87.5 37.95,84.58 38.6,83.93 38.6,78.93 v1(41.1,76.43) ; 40.03,99.52 41.55,101.04 41.55,101.23 41.64,101.31 41.64,102.06 41.61,102.09 41.61,102.4 41.91,102.7 41.91,103.04 42.28,103.4 42.28,103.66 42.23,103.7 v1(42.23,104.08)
GPIO1_28: length 74.3
  TOP w0.121: v1(38.4,102.46) 38.41,102.46 38.97,101.9 38.97,101.46 39.16,101.27 39.16,101.23 40.05,100.34 U5.U18
  LYR4 w0.121: v1(65.42,111.45) 64.75,112.12 55.63,112.12
  LYR4 w0.127: 46.79,107.39 50.62,107.39 51.92,108.69 51.92,110.74 53.29,112.12 55.63,112.12 ; 37.21,101.27 v1(38.4,102.46)
  LYR4 w0.133: v1(38.4,102.46) 38.68,102.74 38.68,103.01 43.06,107.39 46.79,107.39 ; P9.12 33.78,70.53 34.01,70.76 34.01,76.53 35.2,77.73 35.2,78.61 35.71,79.12 35.8,79.12 36.24,79.56 36.24,82.96 36.14,83.06 36.14,83.07 35.97,83.24 35.97,83.35 35.78,83.53 35.78,86.75 35.23,87.3 35.23,88.16 35.99,88.92 35.99,93.37 37.43,94.81 37.43,99.39 37.46,99.42 37.46,99.68 37.21,99.93 37.21,101.27
  BOTTOM w0.121: v1(65.42,111.45) 66.3,111.45 66.5,111.25 R190.1 66.94,110.74 66.96,110.77 R188.2
GPIO1_29: length 34.2
  TOP w0.121: U5.V6 49.92,101.59 49.61,101.9 49.61,103.49 48.95,104.15 48.95,104.17 47.52,105.61 47.52,107.24 47.21,107.55 47.21,110.64 47.89,111.32 47.89,112.69 47.86,112.72 47.86,113.61 48.33,114.08 49.66,114.08 49.85,114.27 51.89,114.27 52.51,114.9 52.51,116.88 P8.26 ; R198.1 59.82,113.79 v1(60.15,114.12)
  LYR3 w0.121: 58.34,114.22 60.05,114.22 v1(60.15,114.12)
  LYR3 w0.133: P8.26 52.86,116.54 57.2,116.54 57.94,115.8 57.94,114.63 58.34,114.22
GPIO2_0: length 17
  BOTTOM w0.121: R208.1 62.2,100.3 61.66,100.85 61.66,101.46 60.93,102.18 60.39,102.18 59.69,102.89 59.69,102.9 59.41,103.18 58.21,103.18 56.53,104.86 56.53,105.35 56.3,105.58 55.97,105.58 55.95,105.56 54.91,105.56 53.21,103.86 R161.2
GPIO2_1: length 41.8
  TOP w0.121: P8.18 40.45,116.88 40.45,114.77 43.43,111.79 43.43,109.5 v1(43.79,109.14) 43.79,108.77 43.99,108.57 43.99,105.87 44.44,105.42 44.44,103.5 44.81,103.12 44.81,102.1 45.12,101.8 U5.V12
  BOTTOM w0.121: v1(43.79,109.14) 44.17,109.14 44.46,109.44 45.25,109.44 45.54,109.73 46.58,109.73 50.48,105.83 52.86,105.83 53.2,106.17 54.61,106.17 54.61,106.17 54.86,106.17 55.23,105.81 55.85,105.81 55.87,105.83 56.4,105.83 58.77,103.46 60.25,103.46 60.88,102.83 60.88,102.67 R207.1
GPIO3_18: length 5.9
  TOP w0.121: U5.B12 44.71,87.93 44.71,87.36 44,86.64 43.49,86.64 42.16,85.32 v1(41.4,85.32)
  BOTTOM w0.121: v1(41.4,85.32) R51.2
GPIO3_19: length 31
  TOP w0.121: v1(43.92,88.73) U5.C13
  LYR4 w0.133: v1(43.92,88.73) 43.25,88.07 43.25,86.8 43.78,86.27 43.78,84.87 44.51,84.14 44.51,80.17 44.32,79.98 44.32,79.16 44.56,78.92 44.76,78.92 44.96,78.92 46.33,77.54 46.33,76.57 46.3,76.55 46.3,76.26 45.9,75.85 45.9,73.51 45.53,73.14 45.53,72.3 47.07,70.76 49.18,70.76 49.98,69.97 49.98,68.31 50.11,68.17 52.96,68.17 P9.27
GPIO3_20: length 5.9
  TOP w0.121: U5.D13 v1(43.92,90.34)
  BOTTOM w0.121: R20.2 43.94,86.08 43.52,86.51 43.52,89.94 v1(43.92,90.34)
GPIO3_21: length 47.7
  TOP w0.121: R167.2 32.26,96.42 v1(32.36,96.32) ; P9.25 50.29,68.3 50.29,69.64 49.4,70.54 47.45,70.54 46.74,71.25 45.69,71.25 45.26,71.68 43.22,71.68 42.85,72.05 42.85,76.02 41.68,77.19 41.68,80.47 40.51,81.64 v1(40.51,85.32) 41.15,85.95 42.13,85.95 43.52,87.34 U5.A14
  LYR3 w0.133: v1(32.36,96.32) 32.28,96.24 32.28,94.44 32.51,94.21 32.51,89.79 34.09,88.21 36.3,88.21 36.91,87.6 36.91,86.44 37.26,86.08 39.37,86.08 40.13,85.32 v1(40.51,85.32)
HDMI_INT: length 15.2
  TOP w0.121: U5.U16 41.52,100.73 41.52,101.97 41.43,102.06 41.43,102.23 40.49,103.17 40.16,103.17 39.55,103.78 36.22,103.78 35.07,102.63 34.05,102.63 33.96,102.54 v1(33.88,102.54)
  BOTTOM w0.121: R169.1 R170.1 32.13,101.68 32.56,101.24 33.63,101.24 33.86,101.47 33.86,102.51 v1(33.88,102.54)
HDMICLK_DISN: length 10.3
  TOP w0.121: U5.V17 41.12,101.17 40.56,101.73 40.56,101.9 40.03,102.43 40.01,102.43 39.25,103.2 36.65,103.2 33.54,100.09 Y4.1
HUB_AVDD: length 5.7
  TOP w0.254: U23.28 28.53,96.6 28.71,96.78 28.71,97.14 v1(28.47,97.38) ; v1(22.12,96.1) U23.9 ; U23.5 25.15,98.47 v1(24.97,98.65) ; U23.14 22.76,93.6 22.48,93.32 22.35,93.32 22.1,93.07 21.59,93.07 C186.2
  TOP w0.381: C186.2 v1(21.46,92.3)
  vias: v2(29.72,90.78) v2(30.35,91.29)
HUB_DM1: length 17.7
  TOP w0.114: J8.A2 14.47,97.95 14.76,97.66 15.12,97.66 15.54,98.08 15.54,100.3 16.48,101.24 17.2,101.24 17.78,101.83 D11.1 18.4,101.33 19.82,101.33 20.8,100.36 24.88,100.36 26.04,99.19 26.04,98.41 26.15,98.3 U23.3
HUB_DM2: length 19
  TOP w0.114: U23.6 24.65,98.3 24.54,98.41 24.54,98.64 24.01,99.17 18.4,99.17 D14.2 17.48,99.24 16.94,99.24 16.51,98.81 16.51,97.92 15.85,97.26 15.85,96.22 15.04,95.4 13.86,95.4 13.36,95.9 13.36,97.18 13,97.54 12.63,97.54 J8.B2
HUB_DM3: length 21.9
  TOP w0.114: U23.12 v1(22.26,94.6) ; v1(19.71,88.82) 19.3,88.42 D17.1 19.76,87.53 19.76,87.39 19.78,87.38 19.78,86.56 19.45,86.23 19.16,86.23 18.4,85.47 18.4,84.64 16.26,82.5 16.26,79.48 15.88,79.1 15.25,79.1 J9.A2
  LYR3 w0.127: v1(19.71,88.82) 19.96,89.08 19.96,93.47 20.9,94.41 22.07,94.41 v1(22.26,94.6)
HUB_DM4: length 23.4
  TOP w0.114: U23.15 24.15,91.89 24.26,91.78 24.26,91.67 23.81,91.21 20.03,91.21 17.63,88.81 17.63,88.37 17.25,87.99 D20.2 17.65,87.48 17.65,86.16 17.25,85.75 17.25,85 15.37,83.12 15.37,81.51 15.06,81.2 13.97,81.2 13.06,80.29 13.06,79.3 12.55,78.79 12.34,78.79 11.85,79.28 J9.B2
HUB_DP1: length 17.7
  TOP w0.114: J8.A3 14.47,97.24 14.59,97.36 14.62,97.36 14.64,97.38 15.24,97.38 15.82,97.97 15.82,100.19 16.6,100.97 17.2,100.97 17.31,100.85 17.31,100.84 17.37,100.79 17.42,100.79 17.65,100.56 D10.1 18.4,101.05 19.71,101.05 20.69,100.08 24.76,100.08 25.76,99.08 25.76,98.41 25.65,98.3 U23.4
HUB_DP2: length 18.9
  TOP w0.114: J8.B3 11.85,96.84 12.27,97.26 12.89,97.26 13.08,97.06 13.08,95.78 13.74,95.12 15.15,95.12 16.13,96.1 16.13,97.14 16.79,97.8 16.79,98.69 17.06,98.96 17.35,98.96 D13.2 18.4,98.89 23.89,98.89 24.26,98.53 24.26,98.41 24.15,98.3 U23.7
HUB_DP3: length 22
  TOP w0.114: J9.A3 14.47,78 15.29,78.82 15.99,78.82 16.54,79.36 16.54,82.38 18.68,84.53 18.68,85.35 19.28,85.95 19.56,85.95 20.06,86.45 20.06,87.47 D16.1 20.57,88.78 v1(20.53,88.82) ; U23.13 22.47,94.1 22.3,93.93 v1(22.22,93.93)
  LYR3 w0.127: v1(20.53,88.82) 20.27,89.08 20.27,93.35 21.03,94.11 22.05,94.11 v1(22.22,93.93)
HUB_DP4: length 23.5
  TOP w0.114: U23.16 24.65,91.89 24.54,91.78 24.54,91.55 23.92,90.93 20.14,90.93 17.91,88.7 17.91,88.49 D19.2 17.93,87.5 17.93,86.04 17.53,85.63 17.53,84.89 15.65,83.01 15.65,81.39 15.18,80.92 14.09,80.92 13.34,80.17 13.34,79.18 12.66,78.51 12.22,78.51 11.85,78.15 J9.B3
HUB_RESET#: length 4.3
  TOP w0.121: v1(25.15,91.18) U23.17
  BOTTOM w0.121: v1(25.15,91.18) 25.4,91.43 C199.1 R228.2 27.3,91.92 R227.1
HUB_VBUS: length 15.9
  BOTTOM w0.381: 7.24,92.91 7.47,92.68 14.88,92.68 16.05,93.85 16.05,97.59 17.11,98.64 FB8.2
I2C0_SCL: length 29.5
  TOP w0.121: v1(28.32,79.16) 28.11,79.37 U2.28 ; v1(41.52,88.73) U5.C16
  LYR4 w0.133: v1(28.32,79.16) 27.58,79.9 27.58,83.54 29.31,85.27 v1(29.31,85.32)
  BOTTOM w0.121: R3.2 27.81,80.62 28.19,80.24 28.19,79.29 v1(28.32,79.16) ; v1(41.52,88.73) 41.12,88.34 41.12,86.81 40.53,86.23 39.07,86.23 37.14,88.16 33.84,88.16 33.83,88.16 32.4,88.16 U7.1 31.5,87.99 30.38,86.87 30.38,85.47 30.23,85.32 v1(29.31,85.32)
I2C0_SDA: length 29.7
  TOP w0.121: v1(28.32,78.52) 27.88,78.97 U2.27 ; U5.C17 40.72,88.74 40.12,88.74 38.73,87.35 38.73,86.54 38.73,86.53 38.73,86.49 37.46,85.22 v1(37.46,84.81)
  LYR3 w0.133: v1(37.46,84.81) 36.2,84.81 34.75,86.26 29.62,86.26 v1(28.65,85.29)
  LYR4 w0.133: v1(28.65,85.29) 27.28,83.92 27.28,79.57 v1(28.32,78.52)
  BOTTOM w0.121: v1(28.65,85.29) 29.13,84.81 29.39,84.81 29.84,84.35 R4.2 30.91,85.37 31.51,85.37 U7.3
I2C1_SCL: length 25.3
  TOP w0.121: U5.A16 v1(41.52,87.13)
  TOP w0.133: P9.17 42.36,67.99 42.36,70.9 41.4,71.86 v1(41.4,72.11)
  LYR4 w0.133: v1(41.4,72.11) 41.4,72.64 44.94,76.18 45.22,76.18 45.6,76.55 45.6,76.84 45.63,76.87 45.63,77.25 44.67,78.21 44.27,78.21 42.87,79.61 42.87,79.88 42.68,80.07 42.68,80.33 42.67,80.34 42.67,80.55 42.63,80.59 42.63,83.79 42.32,84.1 42.32,85.78 41.52,86.58 v1(41.52,87.13)
I2C1_SDA: length 23.5
  TOP w0.121: U5.B16 v1(41.52,87.93)
  LYR4 w0.133: P9.18 40.73,70.25 40.73,72.3 44.84,76.41 45.13,76.41 45.36,76.65 45.36,76.94 45.39,76.96 45.39,77.15 44.57,77.98 44.17,77.98 42.63,79.52 42.63,79.79 42.45,79.97 42.45,80.23 42.43,80.25 42.43,80.35 42.39,80.39 42.39,83.57 42.06,83.9 42.06,85.65 41.11,86.6 41.11,87.53 v1(41.52,87.93)
I2C2_SCL: length 85.7
  TOP w0.121: U5.D17 40.72,89.54 39.9,89.54 38.86,88.49 v1(38.1,88.49) ; J4.1 79.91,86.67 81.13,85.45 v1(82.3,85.45)
  LYR3 w0.133: v1(41.12,78.71) 41.51,78.71 41.64,78.58 45.64,78.58 48.04,76.18 50.02,76.18 50.03,76.18 54.77,76.18 57.08,78.49 69.69,78.49 70.61,79.41 79.64,79.41 81.53,81.31 81.53,84.68 v1(82.3,85.45)
  LYR4 w0.133: P9.19 42.8,68.17 40.82,68.17 40.02,68.97 40.02,74.26 40.67,74.9 42.28,74.9 42.54,75.17 42.54,75.92 40.87,77.6 40.87,78.46 v1(41.12,78.71) 39.07,80.77 39.07,85.9 38.5,86.47 38.5,88.09 v1(38.1,88.49)
  BOTTOM w0.121: v1(82.3,85.45) 82.8,84.94 C202.1
I2C2_SDA: length 83.5
  TOP w0.121: v1(82.17,84.3) 81.8,84.67 J4.2 ; U5.D18 39.8,89.94 38.86,89 38.23,89 v1(38.1,89.13)
  LYR3 w0.133: v1(41.27,77.95) 45.94,77.95 47.95,75.95 49.93,75.95 49.93,75.94 54.87,75.94 57.13,78.21 69.74,78.21 70.71,79.17 79.83,79.17 82.75,82.09 82.75,83.72 v1(82.17,84.3)
  LYR4 w0.133: P9.20 42.99,68.61 41.01,68.61 40.45,69.17 40.45,74.15 40.94,74.65 42.36,74.65 42.78,75.07 42.78,76.12 41.27,77.62 v1(41.27,77.95) 41.55,78.22 41.55,78.86 41.19,79.22 41.06,79.22 39.34,80.93 39.34,86.08 38.73,86.69 38.73,88.49 v1(38.1,89.13)
  BOTTOM w0.121: C203.1 82.68,83.79 v1(82.17,84.3)
JTAG_EMU0: length 22.5
  TOP w0.121: R23.2 37.57,77.66 37.57,78.28 v1(37.44,78.41) ; v1(43.12,88.73) U5.C14
  LYR3 w0.133: v1(37.44,78.41) 38.3,78.41 40.77,80.87 v1(43.81,80.87)
  LYR4 w0.133: v1(43.81,80.87) 44.27,81.33 44.27,83.9 43.46,84.71 43.46,86.21 42.99,86.68 42.99,88.24 43.12,88.36 v1(43.12,88.73)
  BOTTOM w0.121: P2.13 35.8,80.05 v1(37.44,78.41)
JTAG_EMU1: length 15.3
  TOP w0.121: U5.B14 43.12,87.94 43.12,87.29 42.16,86.33 40.89,86.33 39.99,85.43 39.99,81.43 41.05,80.37 v1(41.12,80.37) ; R24.2 37.66,80.24 v1(37.46,80.05)
  BOTTOM w0.121: v1(37.46,80.05) P2.14 40.58,80.05 40.89,80.37 v1(41.12,80.37)
JTAG_TCK: length 24.9
  TOP w0.121: v1(42.55,77.06) 42.06,77.55 42.06,80.72 41.78,81 41.78,84.43 43.75,86.39 44.13,86.39 44.8,87.07 44.8,87.07 45.12,87.38 U5.A12
  LYR3 w0.133: v1(42.55,77.06) 42.1,77.51 36.89,77.51 36.75,77.37 v1(36.75,77.32)
  BOTTOM w0.121: v1(36.75,77.32) 36.56,77.51 36.28,77.51 ; P2.11 35.32,78.78 35.41,78.87 35.86,78.87 36.28,78.45 36.28,77.51 ; 36.28,77.51 P2.9
JTAG_TDI: length 24
  TOP w0.121: v1(43,77.44) 42.44,77.99 42.44,80.94 42.2,81.19 42.2,84.34 43.91,86.05 44.27,86.05 45.52,87.29 45.52,87.94 U5.B11
  BOTTOM w0.121: v1(43,77.44) 43,76.78 42.19,75.97 41.1,75.97 40.73,75.6 37.42,75.6 35.52,73.7 P2.3
JTAG_TDO: length 23.1
  TOP w0.121: v1(43.43,77.01) 43.43,77.6 42.82,78.21 42.82,81.17 42.55,81.44 42.55,84.18 43.94,85.57 43.94,85.57 44.96,85.57 45.59,86.21 45.59,86.84 45.92,87.17 U5.A11
  LYR3 w0.133: v1(43.43,77.01) 43.08,76.66 42.04,76.66 41.71,76.99 37.34,76.99 36.78,76.43 v1(36.78,76.24)
  BOTTOM w0.121: P2.7 v1(36.78,76.24)
JTAG_TMS: length 28.5
  TOP w0.121: v1(46.48,80.87) 46.04,80.43 46.04,75.53 44.74,74.23 44.74,74.16 v1(44.48,73.89) ; U5.C11 v1(45.52,88.73)
  LYR4 w0.133: v1(45.52,88.73) 45.52,87 45.78,86.73 45.78,81.57 v1(46.48,80.87)
  BOTTOM w0.121: P2.1 36.26,72.43 36.98,73.15 41.68,73.15 43.05,74.52 44.22,74.52 44.48,74.27 v1(44.48,73.89)
JTAG_TRSTN: length 25.5
  TOP w0.121: R25.1 38.23,72.69 37.97,72.43 v1(37.46,72.43) ; U5.B10 46.32,87.94 46.32,87.19 45.85,86.72 45.85,86.08 45.09,85.32 44.07,85.32 42.8,84.05 42.8,81.64 43.08,81.36 43.08,78.44 43.89,77.62 43.89,74.42 43.87,74.39 v1(43.87,73.89)
  BOTTOM w0.121: v1(37.46,72.43) P2.2 40.32,72.43 40.51,72.62 41.66,72.62 42.93,73.89 v1(43.87,73.89)
LCD_DATA0: length 34.9
  TOP w0.121: U5.R1 54.03,98.74 55.17,99.87 58.12,99.87 58.42,100.18 58.42,100.56 59.19,101.33 59.32,101.33 v1(59.59,101.6)
  LYR3 w0.133: v1(59.59,101.6) 59.97,101.6 61.14,102.77 61.14,105.56 62.66,107.09 62.66,108.2 64.49,110.03 65.5,110.03 68.04,112.57 71.76,112.57 73.23,114.05 75.72,114.05 P8.45
  BOTTOM w0.121: R70.2 58.19,101.96 58.55,101.6 v1(59.59,101.6) 59.94,101.24 R95.1
LCD_DATA1: length 36.8
  TOP w0.121: U5.R2 53.12,98.75 53.5,99.14 54.08,99.14 54.08,99.14 54.31,99.37 54.31,99.37 55.32,100.38 57.2,100.38 v1(57.25,100.43)
  LYR3 w0.121: 71.7,112.88 73.13,114.3
  LYR3 w0.133: 71.7,112.88 68.02,112.88 65.53,110.39 64.51,110.39 62.28,108.16 62.28,107.11 60.71,105.54 60.71,102.88 59.83,102.01 59.33,102.01 58.01,100.69 57.66,100.69 57.4,100.43 v1(57.25,100.43) ; P8.46 75.57,116.43 75.57,115.08 74.78,114.3 73.13,114.3
  BOTTOM w0.121: R94.1 58.42,100.94 58.29,101.07 R69.2 57.4,100.43 v1(57.25,100.43)
LCD_DATA2: length 70.1
  TOP w0.121: R75.1 R93.1 v1(69.34,83.03) ; v1(52.72,99.14) U5.R3
  LYR3 w0.121: 57.89,100.94 57.15,100.94 56.34,100.13
  LYR3 w0.133: P8.43 73.74,115.29 71.6,113.16 67.96,113.16 65.5,110.69 64.49,110.69 61.98,108.19 61.98,107.27 60.2,105.48 v1(60.2,102.95) 60.12,102.95 59.46,102.29 59.23,102.29 57.89,100.94 ; 56.34,100.13 54,100.13 53.16,99.28 52.98,99.28 52.83,99.14 v1(52.72,99.14) ; v1(70.48,101.17) 72.57,99.08 72.57,91.72 72.42,91.57 72.42,86.23 70.84,84.66 70.84,83.62 70.26,83.03 v1(69.34,83.03)
  LYR4 w0.133: v1(70.48,101.17) 61.98,101.17 v1(60.2,102.95)
  BOTTOM w0.121: R68.2 54.34,100.97 53.73,100.36 52.57,100.36 52.33,100.11 52.33,99.52 v1(52.72,99.14)
LCD_DATA3: length 39.9
  TOP w0.121: v1(51.92,99.14) U5.R4
  LYR3 w0.121: 56.24,100.41 56.27,100.44 56.33,100.44 57.08,101.19 57.78,101.19
  LYR3 w0.133: 57.78,101.19 59.14,102.55 59.14,102.65 v1(59.26,102.77) 59.26,104.88 61.75,107.37 61.75,109.82 63.74,111.81 64.26,111.81 64.52,112.06 66.54,112.06 67.94,113.46 71.4,113.46 73.1,115.16 73.1,116.51 P8.44 ; 56.24,100.41 53.87,100.41 53.01,99.54 52.32,99.54 v1(51.92,99.14)
  BOTTOM w0.121: R92.1 60.96,101.07 v1(59.26,102.77) 58.12,102.77 57.15,103.73 R67.2
LCD_DATA4: length 32.6
  TOP w0.121: U5.T1 54.07,99.54 55.37,100.84 56.16,100.84 v1(56.3,100.98) 56.39,101.07 R91.1 57.48,101.52 57.58,101.52 58.79,102.74 58.79,103.96 58.78,103.98 58.78,105.23 R66.2
  LYR3 w0.133: v1(56.3,100.98) 57,101.68 57,103.05 61.47,107.52 61.47,109.87 63.78,112.19 64.21,112.19 64.47,112.45 66.59,112.45 67.86,113.72 70.31,113.72 P8.41
LCD_DATA5: length 34.8
  TOP w0.121: R65.2 R90.1 58.17,104.24 58.55,103.86 58.55,102.84 57.6,101.89 56.6,101.89 v1(56.34,101.63) 56.26,101.55 55.7,101.55 54.09,99.93 53.51,99.93 U5.T2
  LYR3 w0.133: P8.42 70.61,116.56 70.61,115.21 69.4,114 67.69,114 67.44,113.74 66.01,113.74 65,112.73 64.41,112.73 64.11,112.42 63.44,112.42 61.09,110.07 61.09,107.67 56.34,102.92 v1(56.34,101.63)
LCD_DATA6: length 27.4
  TOP w0.121: v1(52.73,99.95) U5.T3
  LYR3 w0.133: P8.39 68.43,114.38 67.61,114.38 67.23,114 65.79,114 65.28,113.49 64.77,113.49 63.98,112.7 63.38,112.7 59.99,109.31 59.99,107.04 56,103.04 56,102.45 54.41,100.86 53.64,100.86 v1(52.73,99.95)
  BOTTOM w0.121: R64.2 53.92,100.2 53.52,99.8 R89.1 52.85,99.8 52.73,99.92 v1(52.73,99.95)
LCD_DATA7: length 31.8
  TOP w0.121: v1(51.92,99.94) U5.T4
  LYR3 w0.133: v1(51.92,99.94) 53.17,101.19 54.37,101.19 55.63,102.45 55.63,103.07 59.13,106.58 59.13,109.42 59.69,109.98 60.33,109.98 63.36,113 63.83,113 64.55,113.73 65.06,113.73 65.61,114.27 67.14,114.27 67.79,114.93 67.79,116.28 P8.40
  BOTTOM w0.121: v1(51.92,99.94) 51.92,100.18 52.68,100.94 R88.1 53.52,101.12 53.87,101.12 54.48,101.73 R63.2
LCD_DATA8: length 26.5
  TOP w0.121: R62.2 R87.1 57.02,104.24 56.64,103.86 56.64,102.97 56.52,102.84 55.45,102.84 v1(54.91,102.31) 54.91,101.88 54.74,101.7 54.74,100.97 54.11,100.34 U5.U1
  LYR3 w0.133: v1(54.91,102.31) 55.31,102.71 55.31,103.17 58.88,106.73 58.88,107.77 58.89,107.79 58.89,108.12 58.88,108.14 58.88,108.16 58.88,108.17 58.88,108.5 58.88,108.51 58.88,109.7 63.2,114.02 64.97,114.02 65.57,114.61 66.13,114.61 P8.37
LCD_DATA9: length 26.9
  TOP w0.121: U5.U2 53.36,100.34 53.75,100.73 54.12,100.73 54.48,101.09 54.48,102.54 v1(54.84,102.9) 54.99,103.05 54.99,103.1 R61.2 R86.1
  LYR3 w0.133: v1(54.84,102.9) 54.84,103.28 54.61,103.51 54.61,106.98 55.42,107.8 56.29,107.8 58.39,109.91 58.75,109.91 63.12,114.27 64.6,114.27 65.41,115.08 65.41,116.43 P8.38
LCD_DATA10: length 29.1
  TOP w0.121: 53.94,102.53 v1(53.91,102.53) 53.91,102.32 53.77,102.18 53.76,102.18 53.52,101.94 53.52,101.94 53.51,101.93 53.51,100.97 53.28,100.74 52.72,100.74 U5.U3
  TOP w0.133: v1(53.91,102.53) 53.91,103.25 53.7,103.46 R85.1 53.82,103.78 R60.2
  LYR3 w0.133: P8.36 62.92,116.48 62.92,115.13 59.67,111.89 54.87,111.89 54.11,111.13 54.11,108.79 52.84,107.52 52.84,103.17 53.48,102.53 v1(53.91,102.53)
LCD_DATA11: length 25.2
  TOP w0.121: U5.U4 51.92,100.74 51.92,101.68 v1(52.58,102.34)
  LYR3 w0.133: v1(52.58,102.34) 52.31,102.61 52.31,107.75 53.54,108.99 53.54,111.38 54.89,112.73 55.61,112.73 v1(56.19,113.31)
  BOTTOM w0.121: v1(56.19,113.31) 56.21,113.29 56.21,113.12 56.18,113.1 R59.2 56.68,112.65 56.71,112.62 R84.1 57.02,113.95 58.16,115.09 58.16,115.16 58.17,115.16 58.17,115.93 58.67,116.43 60.07,116.43 61.47,117.83 P8.34
LCD_DATA12: length 25.9
  TOP w0.121: U5.V2 53.27,101.29 53.27,102.03 53.28,102.04 53.28,102.05 53.46,102.23 v1(53.46,103.12)
  TOP w0.133: 51.26,105.89 51.26,105.83 51.65,105.44 51.71,105.44 51.92,105.23 52.13,105.23 52.26,105.1 52.26,104.2 R83.1 52.93,103.66 v1(53.46,103.12)
  LYR3 w0.133: v1(53.46,103.12) 54.36,104.01 54.36,110.87 55.02,111.53 59.92,111.53 63.17,114.78 63.75,114.78 P8.35
LCD_DATA13: length 26.3
  TOP w0.121: 52.2,103.25 52.33,103.12 52.38,103.12 52.98,102.51 52.98,102.03 v1(52.63,101.68) 52.32,101.36 U5.V3
  TOP w0.133: 52.2,103.25 52.11,103.34 52.11,103.34 51.71,103.74 R82.1 51.71,104.75 51.11,105.35 50.91,105.35 50.82,105.44 50.76,105.44 50.37,105.83 50.37,105.89
  LYR3 w0.133: v1(52.63,101.68) 52.98,102.03 52.98,102.69 52.6,103.07 52.6,107.65 53.87,108.92 53.87,111.23 54.94,112.29 58.89,112.29 61.05,114.45 61.05,114.61 P8.33
LCD_DATA14: length 25.9
  TOP w0.121: 50.52,104.17 51.21,103.48 51.21,103.27 51.26,103.23 51.26,101.73 51.43,101.55 51.43,101.22 U5.V4 ; P8.31 58.14,116.33 55.7,116.33 55.05,115.68 55.05,114.9 54.5,114.34 53.5,114.34 52.67,113.51 50.14,113.51 49.97,113.33 49.58,113.33 49.02,112.77 49.02,110.96 48.77,110.7 48.77,110.55 49.23,110.1 R81.1 48.75,109.64 48.75,108.27 49.01,108.01 49.01,106.41 49.53,105.89
  TOP w0.133: 50.52,104.17 50.4,104.17 50.3,104.27 50.29,104.27 50.15,104.4 50.15,104.42 49.53,105.04 49.53,105.89
LCD_DATA15: length 28.4
  TOP w0.121: v1(51.12,99.94) U5.T5
  LYR3 w0.121: 49.05,110.1 49.05,110.11 49.85,110.91 49.85,111.93 50.22,112.29 51.26,112.29 51.54,112.57 53.75,112.57 v1(54.39,113.22)
  LYR3 w0.133: 49.05,110.1 48.92,109.97 48.92,108.05 50.75,106.22 50.75,101.65 51.12,101.28 v1(51.12,99.94)
  BOTTOM w0.121: P8.32 59.05,117.83 57.91,116.69 57.91,115.19 57,114.27 56.26,114.27 55.75,113.77 54.94,113.77 v1(54.39,113.22) 54.74,112.87 R80.1 R55.2
LCD_DE: length 10.2
  BOTTOM w0.121: R48.2 49.91,113.26 50.85,114.2 54.91,114.2 55.37,114.66 55.37,116.56 56.64,117.83
LCD_HSYNC: length 7.8
  TOP w0.121: 56.64,115.29 55.97,114.62 55.12,114.62 54.6,114.09 53.61,114.09 52.78,113.26 50.4,113.26 50.36,113.23 50.3,113.23 49.91,112.84 R47.2
LCD_PCLK: length 15
  TOP w0.121: 48.29,107.16 48.29,107.23 47.71,107.8 47.71,110.4 48.51,111.2 48.51,113 49.34,113.83 49.76,113.83 49.96,114.03 50.73,114.03 50.73,114.02 51.98,114.02 53.09,115.12 53.09,116.81 P8.28
LCD_VSYNC: length 9.4
  TOP w0.121: P8.27 52.58,113.77 50.84,113.77 50.82,113.76 50.04,113.76 49.86,113.58 49.44,113.58 48.76,112.9 48.76,111.1 48.29,110.62 48.29,110.59 48.26,110.56 R46.2
LCDDE: length 14.7
  TOP w0.121: v1(50.32,99.14) U5.R6
  LYR3 w0.121: v1(50.32,99.14) 50.72,99.54 50.72,100.3
  LYR3 w0.133: 50.72,100.3 50.72,100.69 49.78,101.62 49.78,106.71 48.64,107.85 48.64,110.27 v1(49.45,111.08)
  BOTTOM w0.121: R48.1 49.91,111.54 v1(49.45,111.08)
LCDPCLK: length 6.1
  TOP w0.121: U5.V5 50.72,103.15 50.69,103.17 50.69,103.26 50.44,103.51 50.31,103.51 49.44,104.38 48.29,105.54 R45.1
LCDVHYNC: length 15.5
  TOP w0.121: v1(51.12,99.14) U5.R5 ; R47.1 v1(50.5,111.76)
  LYR3 w0.121: v1(50.5,111.76) 50.5,111.23 49.28,110.01 49.28,110.01 49.16,109.88 49.16,108.2 ; v1(51.12,99.14) 51.52,99.54 51.52,100.1 51.51,100.11 51.51,100.46
  LYR3 w0.133: 49.16,108.2 50.98,106.37 50.98,102.09 51.01,102.06 51.01,101.76 51.38,101.39 51.38,100.59 51.51,100.46
LCDVSYNC: length 10.1
  TOP w0.121: U5.U5 51.12,100.74 51.12,101.41 50.96,101.56 50.96,103.25 50.94,103.27 50.94,103.36 50.54,103.76 50.45,103.76 50.2,104.01 50.18,104.01 49.9,104.3 49.9,104.31 48.76,105.45 48.76,107.79 48.29,108.27 R46.1
LDO_PGOOD: length 35.5
  TOP w0.121: U5.B5 v1(51.12,87.93) ; v1(22.22,84.75) 22.86,84.12 U2.46
  LYR3 w0.133: v1(51.12,87.93) 51.12,85.64 50.8,85.32 48.74,85.32 47.75,84.33 39.57,84.33 38.68,85.22 36.3,85.22 34.95,86.56 29.13,86.56 28.02,85.45 22.92,85.45 v1(22.22,84.75)
LEDAA: length 1.9
  TOP w0.254: D2.2 7.18,115.48 v1(7.87,114.78)
  BOTTOM w0.254: v1(7.87,114.78) R72.2
LEDAC: length 18.1
  TOP w0.121: D2.1 5.89,115.67 v1(6.24,115.33) ; v1(20.7,110.85) 20.7,110.56 20.69,110.54 Q1.6
  LYR3 w0.133: v1(6.24,115.33) 7.97,115.33 10.19,113.11 17.55,113.11 19.81,110.85 v1(20.7,110.85)
LEDBA: length 1.5
  TOP w0.254: v1(7.89,113.89) D3.2
  BOTTOM w0.254: R73.2 v1(7.89,113.89)
LEDBC: length 20.1
  TOP w0.121: v1(6.6,113) 5.71,113.89 D3.1 ; Q1.3 21.99,108.7 22.22,108.94 v1(22.61,108.94)
  LYR3 w0.133: v1(6.6,113) 6.63,113.03 7.4,113.03 7.71,112.73 17.3,112.73 21.08,108.94 v1(22.61,108.94)
LEDCA: length 2.5
  TOP w0.254: D4.2 7.18,111.93 7.87,112.62 v1(7.87,113.13)
  BOTTOM w0.254: R74.2 8,113 v1(7.87,113.13)
LEDCC: length 16.1
  TOP w0.121: v1(4.7,111.23) 5.02,111.23 D4.1 ; v1(17.02,110.72) 17.4,110.34 17.91,110.34 18.02,110.23 Q2.6
  LYR3 w0.133: v1(4.7,111.23) 8.13,111.23 9.35,112.45 15.29,112.45 v1(17.02,110.72)
LEDDA: length 3.1
  TOP w0.254: v1(7.95,111.89) 8,111.84 8,110.85 7.18,110.02 D5.2
  BOTTOM w0.305: R71.2 8.18,112.12 v1(7.95,111.89)
